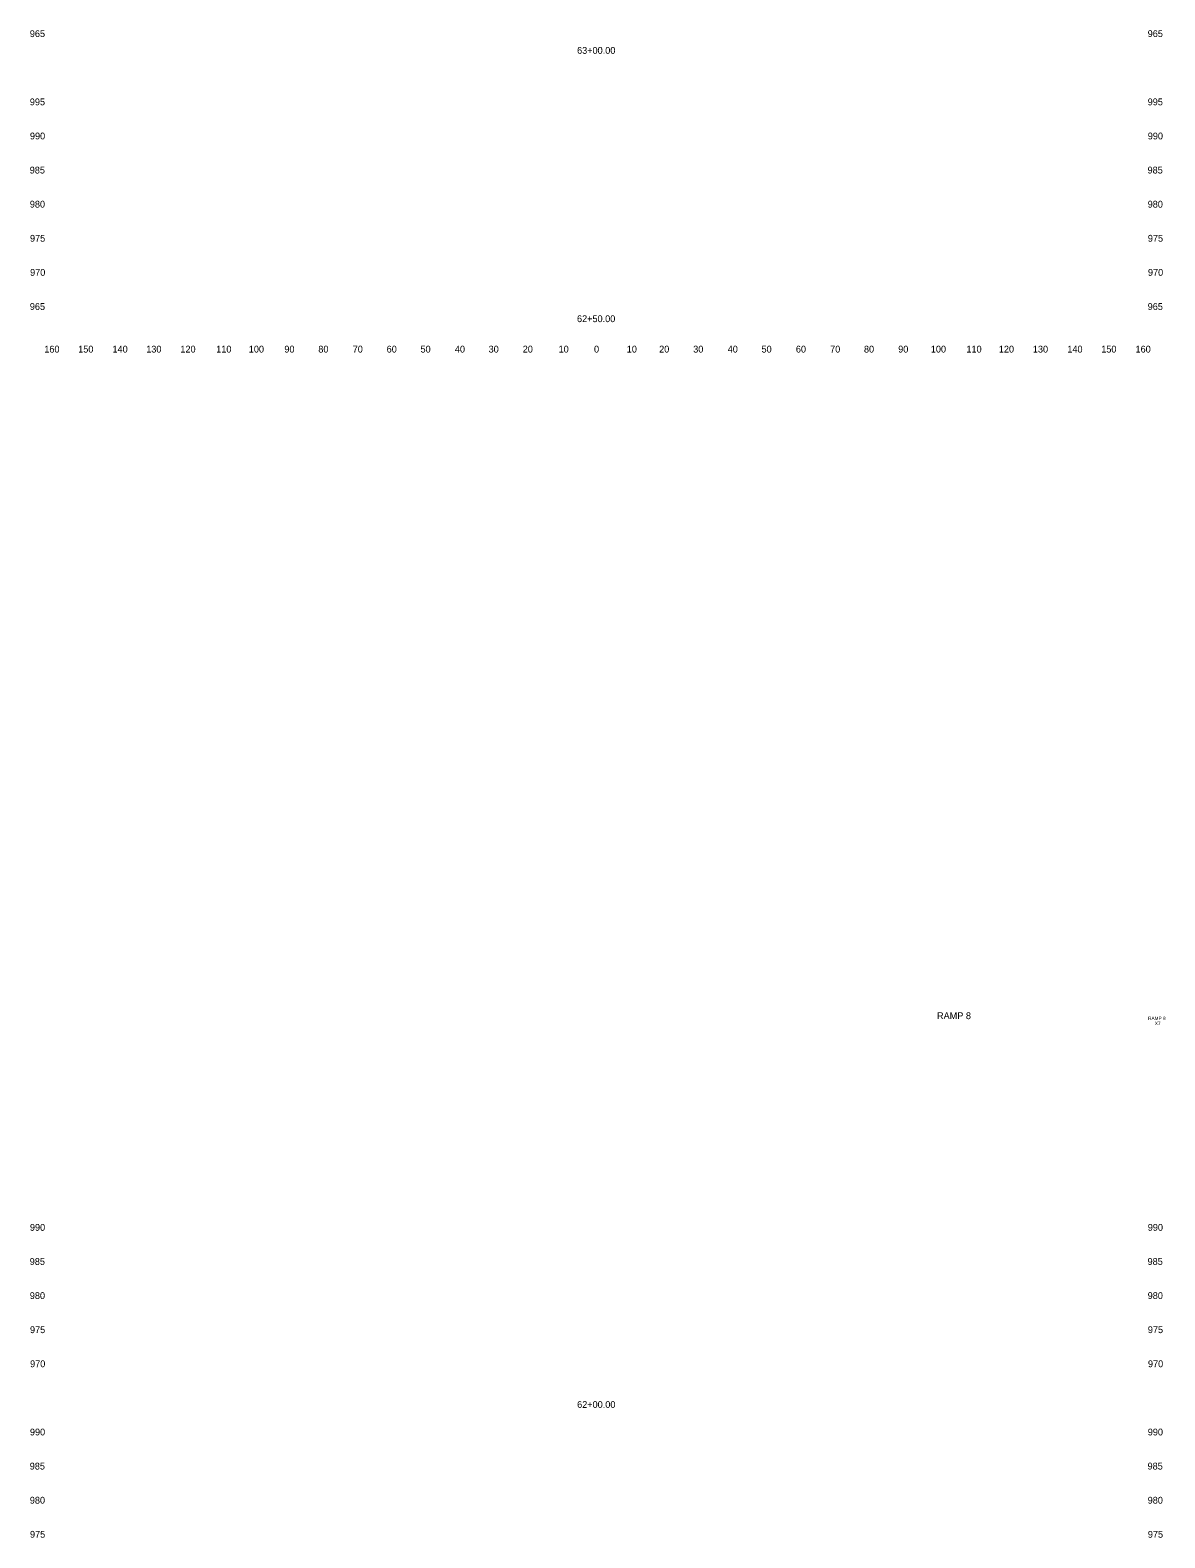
# Model space of a CAD drawing. Extents: x 4994 to 5843, y 4997 to 8804.
# Drawn here: x 4994 to 5326.7, y 7450 to 7892 of the extents above; entities that cross this region are included whole.
import ezdxf

# ---------------------------------------------------------------- set-up
doc = ezdxf.new("R2010")
doc.units = 0
for name, color, linetype in [('RD_SHT_ID', 7, 'Continuous'), ('RD_XS_TX_Offset', 7, 'Continuous'), ('RD_XS_TX_Station', 7, 'Continuous')]:
    doc.layers.add(name, color=color, linetype=linetype)

msp = doc.modelspace()

# ---------------------------------------------------------------- texts
at = {"layer": 'RD_SHT_ID'}
for s, height, p in [('RAMP 8', 2, (5259.88, 7602.06)), ('RAMP 8', 1, (5321.78, 7601.8)), ('X7', 1, (5323.74, 7600.3))]:
    msp.add_text(s, height=height, dxfattribs=at).set_placement(p)
at = {"layer": 'RD_XS_TX_Offset'}
for s, p in [('965', (4993.86, 7890)), ('965', (5321.66, 7890)), ('995', (4993.86, 7870)), ('995', (5321.66, 7870)), ('990', (4993.89, 7860)), ('990', (5321.69, 7860)), ('985', (4993.83, 7850)), ('985', (5321.63, 7850)), ('980', (4993.86, 7840)), ('980', (5321.66, 7840)), ('975', (4993.91, 7830)), ('975', (5321.71, 7830)), ('970', (4993.94, 7820)), ('970', (5321.74, 7820)), ('965', (4993.86, 7810)), ('965', (5321.66, 7810)), ('160', (4998.1, 7797.5)), ('150', (5008.04, 7797.5)), ('140', (5018.1, 7797.5)), ('130', (5027.99, 7797.5)), ('120', (5038.01, 7797.5)), ('110', (5048.51, 7797.5)), ('100', (5058.07, 7797.5)), ('90', (5068.5, 7797.5)), ('80', (5078.46, 7797.5)), ('70', (5088.54, 7797.5)), ('60', (5098.5, 7797.5)), ('50', (5108.43, 7797.5)), ('40', (5118.5, 7797.5)), ('30', (5128.39, 7797.5)), ('20', (5138.4, 7797.5)), ('10', (5148.91, 7797.5)), ('0', (5159.3, 7797.5)), ('0', (5159.3, 7797.5)), ('10', (5168.91, 7797.5)), ('20', (5178.4, 7797.5)), ('30', (5188.39, 7797.5)), ('40', (5198.5, 7797.5)), ('50', (5208.43, 7797.5)), ('60', (5218.5, 7797.5)), ('70', (5228.54, 7797.5)), ('80', (5238.46, 7797.5)), ('90', (5248.5, 7797.5)), ('100', (5258.07, 7797.5)), ('110', (5268.51, 7797.5)), ('120', (5278.01, 7797.5)), ('130', (5287.99, 7797.5)), ('140', (5298.1, 7797.5)), ('150', (5308.04, 7797.5)), ('160', (5318.1, 7797.5)), ('990', (4993.89, 7540)), ('990', (5321.69, 7540)), ('985', (4993.83, 7530)), ('985', (5321.63, 7530)), ('980', (4993.86, 7520)), ('980', (5321.66, 7520)), ('975', (4993.91, 7510)), ('975', (5321.71, 7510)), ('970', (4993.94, 7500)), ('970', (5321.74, 7500)), ('990', (4993.89, 7480)), ('990', (5321.69, 7480)), ('985', (4993.83, 7470)), ('985', (5321.63, 7470)), ('980', (4993.86, 7460)), ('980', (5321.66, 7460)), ('975', (4993.91, 7450)), ('975', (5321.71, 7450))]:
    msp.add_text(s, height=2, dxfattribs=at).set_placement(p)
at = {"layer": 'RD_XS_TX_Station'}
for s, p in [('63+00.00', (5154.34, 7885.09)), ('62+50.00', (5154.32, 7806.42)), ('62+00.00', (5154.35, 7488.07))]:
    msp.add_text(s, height=2, dxfattribs=at).set_placement(p)

doc.saveas('drawing.dxf')
